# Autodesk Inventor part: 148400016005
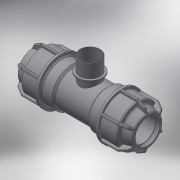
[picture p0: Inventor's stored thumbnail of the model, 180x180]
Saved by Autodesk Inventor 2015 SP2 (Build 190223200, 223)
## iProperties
Created: 2017-08
Part Number: 148400016005
Material: Generic
Description: PLASSON L.14 TEE MALE ADAPTOR (SILVER) 16-1/2"-16(20)
Document SubType Name: Modeling
Designer: KIM
Density: 1 g/cm^3
Appearance: Default
Author: KIM
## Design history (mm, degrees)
derived "148400.ipt"
feature "Solid1::148400.ipt"
feature "Solid2::148400.ipt"
tag "TaggingFeature1"
body "Solid1"
body "Solid2"
other parameters: "d1" = 16, "d2" = 44, "d4" = 15 deg, "d5" = 29.04, "d6" = 9.5832, "d10" = 42, "d16" = 16.32, "d17" = 2.2, "d22" = 25.6, "d24" = 2.2, "d25" = 37.8, "d26" = 31.5, "d27" = 2.2, "d28" = 135 deg, "d29" = 1.32, "d31" = 0.8, "d46" = 150 deg, "d49" = 2.1, "d50" = 0, "d58" = 0.48, "d61" = 360 deg, "d63" = 14.4, "d64" = 56.5, "d80" = 23.04, "d81" = 1.28, "d84" = 2.2, "d94" = 44, "d96" = 20.955, "d108" = 0.48, "d111" = 0, "d113" = 14.4, "d114" = 25.146, "d115" = 17, "d116" = 1.7, "d117" = 20.955, "d_" = 16, "R_" = 20.955, "E_" = 42, "H_" = 113, "l_" = 44, "l_2" = 17, "A_" = 44
